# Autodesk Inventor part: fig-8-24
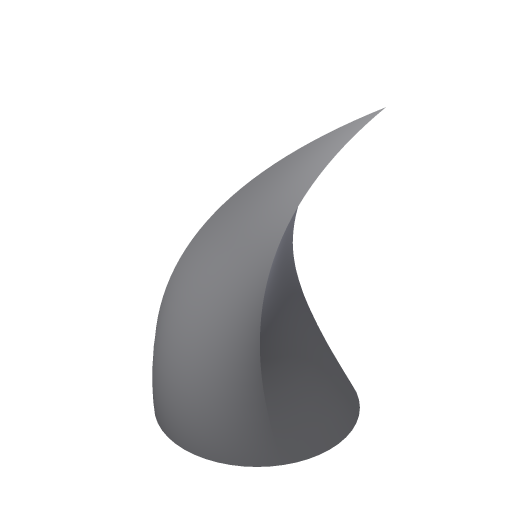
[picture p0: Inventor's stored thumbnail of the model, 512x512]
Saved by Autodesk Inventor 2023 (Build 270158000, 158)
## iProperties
Created: 2001-12
Part Number: fig-8-24
Document SubType Name: Modeling
Designer: CADSoft
Density: 1 g/cm^3
Material: Generic
Appearance: Default
Control State: 0
Master: False
Checked Out: False
Shininess: 77.0
Angle Display Precision: 2
Document Length Units: 11269
Document Angle Units: 11279
Document Time Units: 11290
Document Mass Units: 11283
Document Length Units Precision: 3
Document Angle Units Precision: 2
Density: 0.0
Volumn: 0.0
Area: 0.0
PropertySet Name: Model Information
Author: CADSoft
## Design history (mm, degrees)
workplane "Work Plane3"
workplane "Work Plane4"
sketch "Sketch12"
  geometry: L1 (0, 10.598)-(9.178, -5.299); L2 (9.178, -5.299)-(-9.178, -5.299); L3 (-9.178, -5.299)-(0, 10.598); 1 further point
  constraints: 6 end point, 5 other
workplane "Work Plane5"
loft "Loft5" dims "d57" = 0, "d58" = 90 deg, "d59" = 0, "d60" = 90 deg, "d61" = 0, "d62" = 90 deg
body "Solid1"
sketch "Sketch1"
  geometry: C1 r 19.387 at (0, 0); 1 further point
  constraints: 1 centre point, 1 coincident, 1 other
sketch "Sketch2"
  geometry: 1 further point
